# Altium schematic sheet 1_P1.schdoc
size 307 x 218 mm; Symbol: Sheet-Symbol_A4; Device: Sheet-Symbol_A4; Company: 嘉立创EDA; Version: V1.0; Page Size: A4; @Project Name: CASA0021; @Page Count: 1; @Update Date: 2025-02-10; @Create Date: 2025-02-08; @Schematic Name: Schematic1; @Page No: 1; @Page Name: P1; @Board Name: 加热底板; @Create Time: 18:02:16; @Update Time: 02:10:29; Width: 1170; Height: 825; Region Start: 1; X Region Count: 6; Y Region Count: 4; Blade Width: 10; Title Block Position: 3
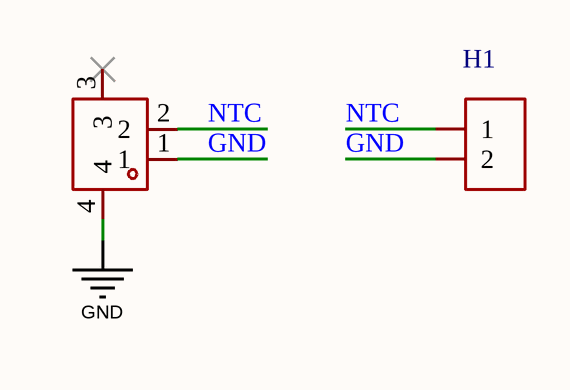
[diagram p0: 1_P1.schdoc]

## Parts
FAN1  WAFER-MX1.25-2PWB  [CONN-SMD_2P-P1.25_XUNPU_WAFER-MX1.25-2PWB]  (value not drawn)
H1  (no value)  [HDR-TH_2P-P2.54-V-F]

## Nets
GND: FAN1.1 FAN1.4 H1.2
NTC: FAN1.2 H1.1

Not connected (* = marked no-connect by the designer): FAN1 3*

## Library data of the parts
FAN1 = WAFER-MX1.25-2PWB: Manufacturer: XUNPU(讯普); Add into BOM: yes; Pins Structure: 1x2P; Pitch: 1.25mm; Number of PINs Per Row: 2; Current Rating (Max): 1A
H1 = HDR-F_2.54_1x2P: Manufacturer: BOOMELE(博穆精密); Manufacturer Part: 2.54-1*2P母; Symbol: Header-Female-2.54_1x2; Convert to PCB: yes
